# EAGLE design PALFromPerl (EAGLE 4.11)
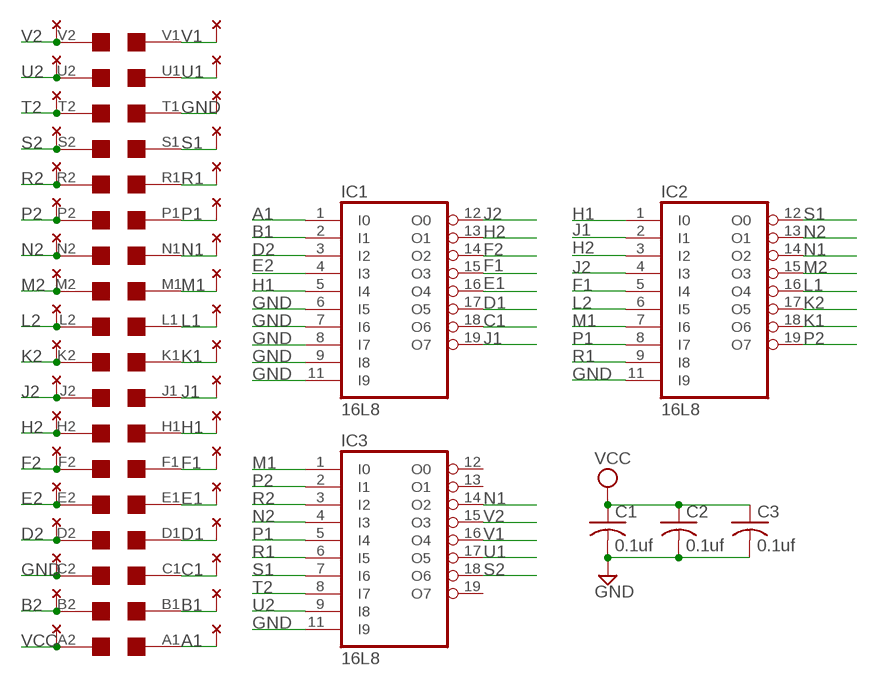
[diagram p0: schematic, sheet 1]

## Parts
C1  0.1uf  C-US050-025X075  [C050-025X075]
C2  0.1uf  C-US050-025X075  [C050-025X075]
C3  0.1uf  C-US050-025X075  [C050-025X075]
IC1  16L8  [DIL20]
IC2  16L8  [DIL20]
IC3  16L8  [DIL20]
U$1  EDGE-2  [EDGE-CON2]
U$4  THRU-HOLE2  [THRU-HOLEB]

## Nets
A1: IC1.1(I0) U$1.A1 U$4.A2
B1: IC1.2(I1) U$1.B1 U$4.B2
B2: U$1.B2 U$4.B1
C1: IC1.18(O6) U$1.C1 U$4.C2
D1: IC1.17(O5) U$1.D1 U$4.D2
D2: IC1.3(I2) U$1.D2 U$4.D1
E1: IC1.16(O4) U$1.E1 U$4.E2
E2: IC1.4(I3) U$1.E2 U$4.E1
F1: IC1.15(O3) IC2.5(I4) U$1.F1 U$4.F2
F2: IC1.14(O2) U$1.F2 U$4.F1
GND: C1.2 C2.2 C3.2 IC1.6(I5) IC1.7(I6) IC1.8(I7) IC1.9(I8) IC1.11(I9) IC2.11(I9) IC3.11(I9) U$1.C2 U$1.T1 U$4.C1 U$4.T2
H1: IC1.5(I4) IC2.1(I0) U$1.H1 U$4.H2
H2: IC1.13(O1) IC2.3(I2) U$1.H2 U$4.H1
J1: IC1.19(O7) IC2.2(I1) U$1.J1 U$4.J2
J2: IC1.12(O0) IC2.4(I3) U$1.J2 U$4.J1
K1: IC2.18(O6) U$1.K1 U$4.K2
K2: IC2.17(O5) U$1.K2 U$4.K1
L1: IC2.16(O4) U$1.L1 U$4.L2
L2: IC2.6(I5) U$1.L2 U$4.L1
M1: IC2.7(I6) IC3.1(I0) U$1.M1 U$4.M2
M2: IC2.15(O3) U$1.M2 U$4.M1
N1: IC2.14(O2) IC3.14(O2) U$1.N1 U$4.N2
N2: IC2.13(O1) IC3.4(I3) U$1.N2 U$4.N1
P1: IC2.8(I7) IC3.5(I4) U$1.P1 U$4.P2
P2: IC2.19(O7) IC3.2(I1) U$1.P2 U$4.P1
R1: IC2.9(I8) IC3.6(I5) U$1.R1 U$4.R2
R2: IC3.3(I2) U$1.R2 U$4.R1
S1: IC2.12(O0) IC3.7(I6) U$1.S1 U$4.S2
S2: IC3.18(O6) U$1.S2 U$4.S1
T2: IC3.8(I7) U$1.T2 U$4.T1
U1: IC3.17(O5) U$1.U1 U$4.U2
U2: IC3.9(I8) U$1.U2 U$4.U1
V1: IC3.16(O4) U$1.V1 U$4.V2
V2: IC3.15(O3) U$1.V2 U$4.V1
VCC: C1.1 C2.1 C3.1 U$1.A2 U$4.A1
Unconnected: IC3.12(O0) IC3.13(O1) IC3.19(O7)

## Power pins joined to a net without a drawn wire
GND: IC1.10(GND) IC2.10(GND) IC3.10(GND)
VCC: IC1.20(VCC) IC2.20(VCC) IC3.20(VCC)

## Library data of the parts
C1-C3 = rcl:C-US: CAPACITOR, American symbol
IC1-IC3 = pal:16L8: PAL
U$1 = dec-con:EDGE-2: Double-Sided DEC edge connector.
U$4 = dec-con:THRU-HOLE2: Thru-Hole addition to double-sided edge connector.

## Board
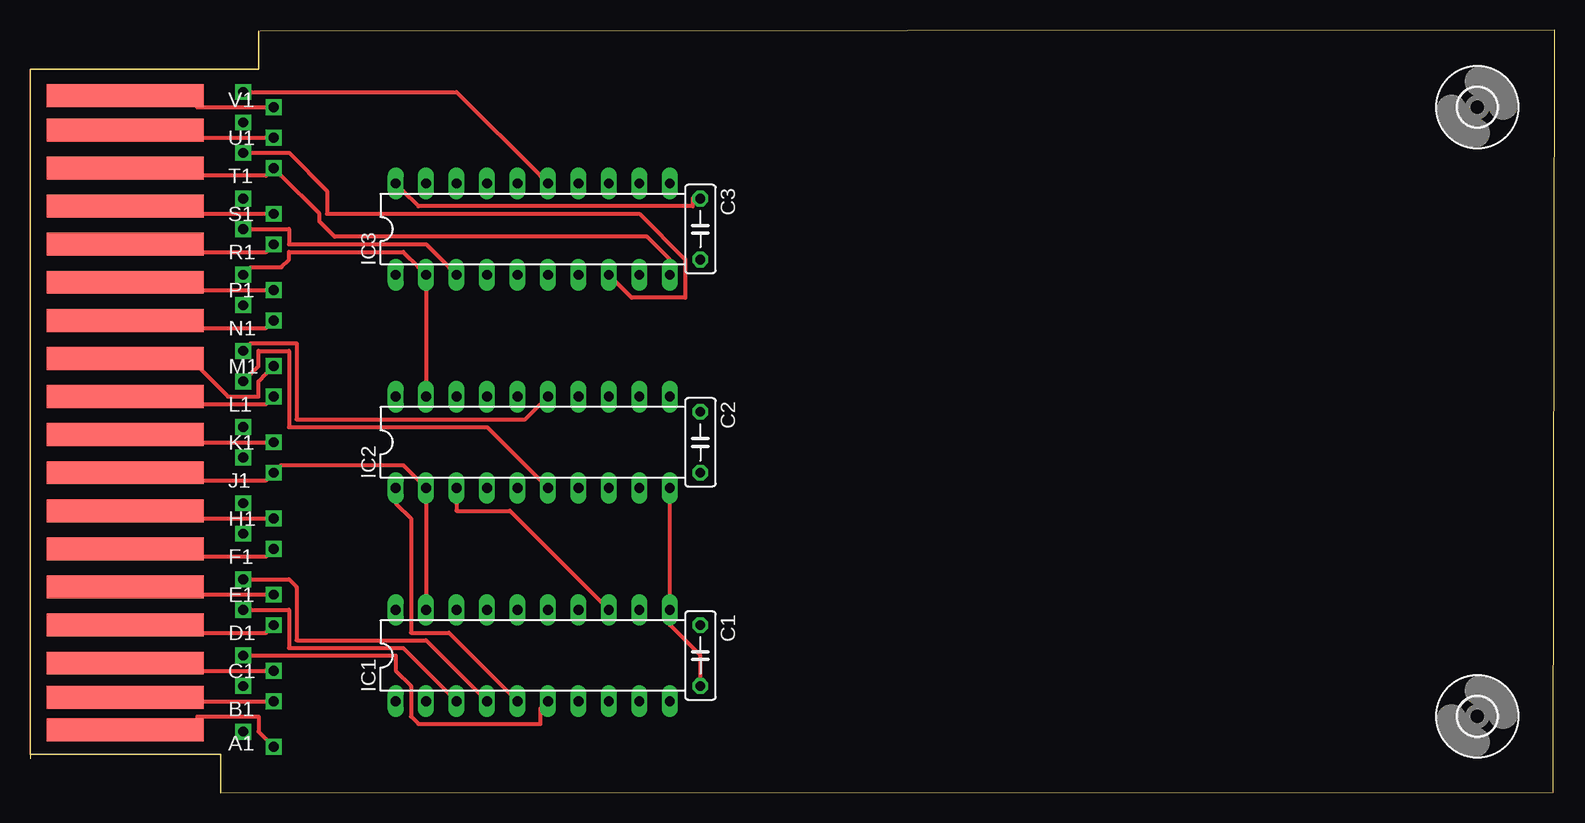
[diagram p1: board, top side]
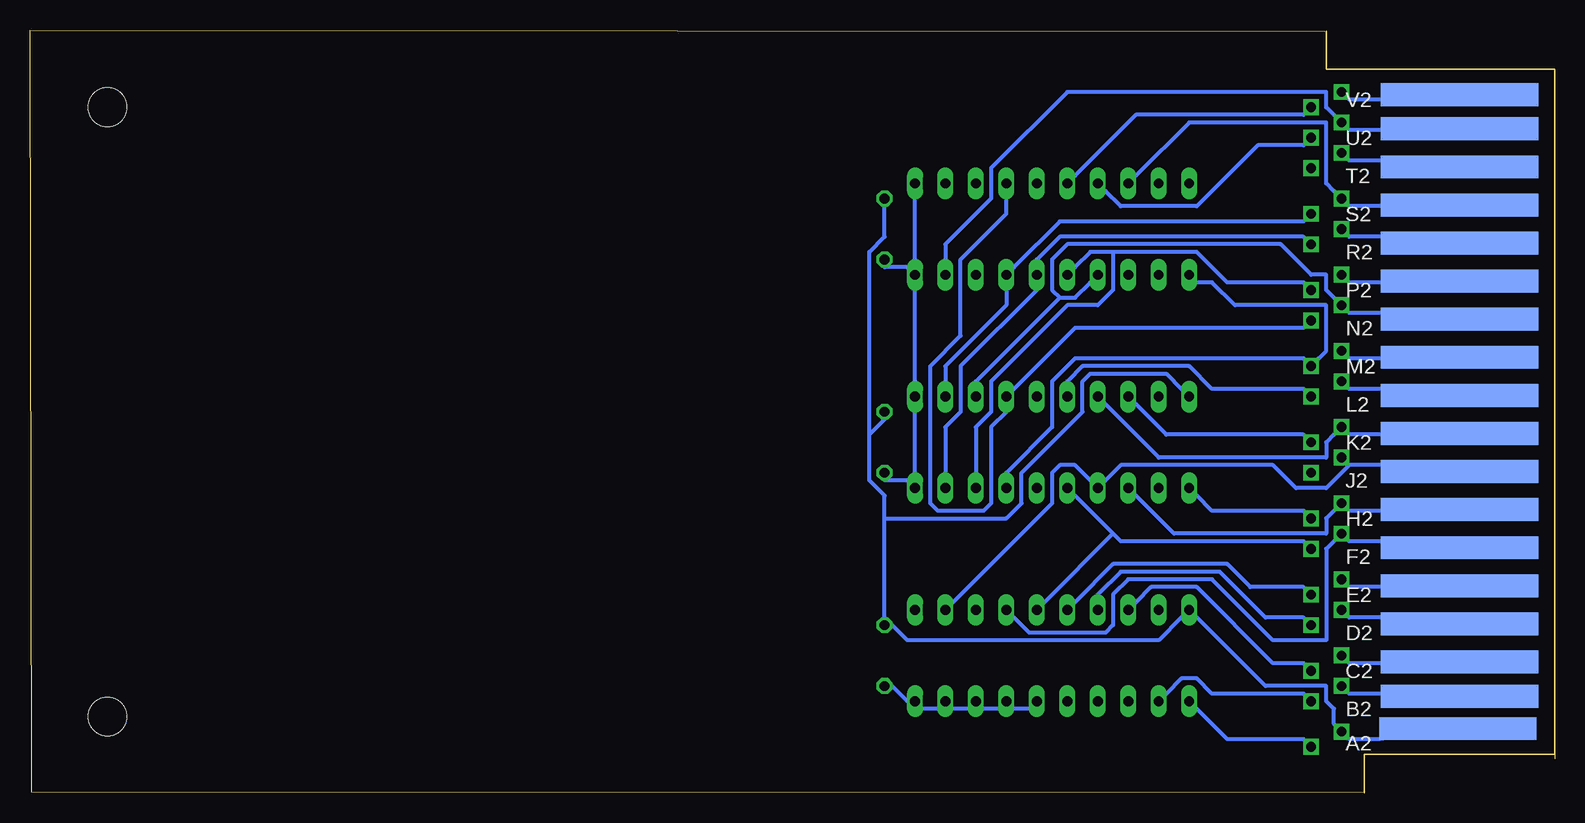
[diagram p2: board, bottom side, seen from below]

Size 127.11 x 63.59 mm. Coordinates in mm from the lower left corner, seen from the top.
Outline: 15.88,0 126.98,0.04 127.11,63.59 19.18,63.5
Outline: 0.01,59.65 0.01,2.83
Copper layers (1*16): Top 0.035mm / dielectric 1.5mm / Bottom 0.035mm
Design rules "10mils": minimum track width 13mil, minimum drill 28mil, track to track 10mil, track to pad 10mil, pad to pad 10mil, via to via 10mil, smd to smd 10mil, copper to edge 40mil, drill to drill 10mil, minimum pad ring 10mil, minimum via ring 8mil, stop-mask expansion 0mil, vias tented up to drill 0mil, thermal gap 10mil

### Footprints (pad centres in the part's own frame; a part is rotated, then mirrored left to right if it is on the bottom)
C050-025X075 = drill 0.813 octagon: 1 -2.54,0; 2 2.54,0
DIL20 = drill 0.813 long: 1 -11.43,-3.81; 2 -8.89,-3.81; 3 -6.35,-3.81; 4 -3.81,-3.81; 5 -1.27,-3.81; 6 1.27,-3.81; 7 3.81,-3.81; 8 6.35,-3.81; 9 8.89,-3.81; 10 11.43,-3.81; 11 11.43,3.81; 12 8.89,3.81; 13 6.35,3.81; 14 3.81,3.81; 15 1.27,3.81; 16 -1.27,3.81; 17 -3.81,3.81; 18 -6.35,3.81; 19 -8.89,3.81; 20 -11.43,3.81
EDGE-CON2 = smd 13.106 x 1.905: A1 7.938,5.239; B1 7.938,7.938; C1 7.938,10.795; D1 7.938,13.97; E1 7.938,17.145; F1 7.938,20.32; H1 7.938,23.495; J1 7.938,26.67; K1 7.938,29.845; L1 7.938,33.02; M1 7.938,36.195; N1 7.938,39.37; P1 7.938,42.545; R1 7.938,45.72; S1 7.938,48.895; T1 7.938,52.07; U1 7.938,55.245; V1 7.938,58.102 | smd 13.106 x 1.905 bottom: A2 8.096,5.34; B2 7.938,8.039; C2 7.938,10.897; D2 7.938,14.072; E2 7.938,17.247; F2 7.938,20.422; H2 7.938,23.597; J2 7.938,26.772; K2 7.938,29.947; L2 7.938,33.122; M2 7.938,36.297; N2 7.938,39.472; P2 7.938,42.647; R2 7.938,45.822; S2 7.938,48.997; T2 7.938,52.172; U2 7.938,55.347; V2 7.938,58.204
3,2 = hole 3.2: 0,0
THRU-HOLEB = drill 0.813 square: A1 17.78,5.08; A2 20.32,3.81; B1 17.78,8.89; B2 20.32,7.62; C1 17.78,11.43; C2 20.32,10.16; D1 17.78,15.24; D2 20.32,13.97; E1 17.78,17.78; E2 20.32,16.51; F1 17.78,21.59; F2 20.32,20.32; H1 17.78,24.13; H2 20.32,22.86; J1 17.78,27.94; J2 20.32,26.67; K1 17.78,30.48; K2 20.32,29.21; L1 17.78,34.29; L2 20.32,33.02; M1 17.78,36.83; M2 20.32,35.56; N1 17.78,40.64; N2 20.32,39.37; P1 17.78,43.18; P2 20.32,41.91; R1 17.78,46.99; R2 20.32,45.72; S1 17.78,49.53; S2 20.32,48.26; T1 17.78,53.34; T2 20.32,52.07; U1 17.78,55.88; U2 20.32,54.61; V1 17.78,58.42; V2 20.32,57.15

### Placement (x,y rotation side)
C1  55.88,11.43 270 top
C2  55.88,29.21 270 top
C3  55.88,46.99 270 top
IC1  41.91,11.43 0 top
IC2  41.91,29.21 0 top
IC3  41.91,46.99 0 top
U$1  0,0 0 top
U$2  [3,2]  120.65,6.35 0 top
U$3  [3,2]  120.65,57.15 0 top
U$4  0,0 0 top

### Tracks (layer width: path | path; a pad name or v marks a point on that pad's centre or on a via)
A1
  Top 0.33: U$4.A2 19.68,4.45 19.05,5.08 19.05,6.35 13.97,6.35 13.97,5.71 U$1.A1
  Bottom 0.33: U$4.A2 20.95,4.45 27.3,4.45 29.84,6.99 IC1.1
B1
  Top 0.33: U$4.B2 19.68,7.62 13.97,7.62 U$1.B1
  Bottom 0.33: U$4.B2 20.95,8.26 28.57,8.26 29.84,9.53 31.11,9.53 32.38,8.26 IC1.2
B2
  Bottom 0.33: U$4.B1 17.14,8.26 13.97,8.26 U$1.B2
C1
  Top 0.33: U$4.C2 19.68,10.16 13.97,10.16 U$1.C1
  Bottom 0.33: U$4.C2 20.95,10.79 23.5,10.79 29.84,17.14 33.66,17.14 34.92,15.88 IC1.18
D1
  Top 0.33: U$4.D2 19.68,13.34 13.97,13.34 U$1.D1
  Bottom 0.33: U$4.D2 20.95,14.61 24.13,14.61 27.94,18.41 36.2,18.41 38.1,16.51 IC1.17
D2
  Top 0.33: IC1.3 34.92,8.26 31.11,12.06 21.59,12.06 21.59,15.24 18.41,15.24 U$4.D1
  Bottom 0.33: U$4.D1 17.14,14.61 13.97,14.61 U$1.D2
E1
  Top 0.33: U$4.E2 19.68,16.51 13.97,16.51 U$1.E1
  Bottom 0.33: U$4.E2 20.95,17.14 25.4,17.14 27.3,19.05 36.83,19.05 40.01,15.88 IC1.16
E2
  Top 0.33: IC1.4 37.47,8.26 33.02,12.7 22.23,12.7 22.23,17.14 21.59,17.78 18.41,17.78 U$4.E1
  Bottom 0.33: U$4.E1 17.14,17.14 13.97,17.14 U$1.E2
F1
  Top 0.33: U$1.F1 13.97,19.68 19.68,19.68 U$4.F2
  Bottom 0.33: 36.83,21.59 40.01,24.77 IC2.5 | 36.83,21.59 36.2,20.95 20.95,20.95 U$4.F2 | 36.83,21.59 42.55,15.88 IC1.15
F2
  Bottom 0.33: U$1.F2 13.97,20.95 17.14,20.95 U$4.F1 18.41,20.95 19.05,20.32 19.05,12.7 23.5,12.7 28.57,17.78 35.56,17.78 36.83,16.51 36.83,13.97 37.47,13.34 43.81,13.34 45.09,14.61 IC1.14
GND
  Top 0.33: U$1.T1 13.97,51.44 19.68,51.44 U$4.T2 20.95,51.44 24.13,48.26 24.13,47.62 25.4,46.35 51.44,46.35 53.34,44.45 IC3.10 | C1.2 55.88,9.53 55.88,11.43 53.34,13.97 IC1.11 53.34,16.51 53.34,24.13 IC2.10 | U$4.C1 18.41,11.43 30.48,11.43 30.48,10.16 31.75,8.89 31.75,6.35 32.38,5.71 42.55,5.71 42.55,6.99 IC1.6
  Bottom 0.33: U$4.C1 17.14,10.79 13.97,10.79 U$1.C2 | IC1.6 43.81,6.99 45.09,6.99 IC1.7 46.35,6.99 47.62,6.99 IC1.8 48.9,6.99 50.16,6.99 IC1.9 51.44,6.99 52.7,6.99 IC1.10 53.98,7.62 55.24,8.89 C1.2 | IC3.10 53.98,43.81 55.88,43.81 C3.2 | C2.2 55.88,26.04 53.98,26.04 IC2.10 53.34,26.67 53.34,31.75 IC2.11 53.34,34.29 53.34,41.91 IC3.10 | IC3.11 53.34,49.53 53.34,44.45 IC3.10
H1
  Top 0.33: IC1.5 40.01,8.26 34.92,13.34 31.75,13.34 31.75,22.86 30.48,24.13 IC2.1 | U$1.H1 13.97,22.86 19.68,22.86 U$4.H2
  Bottom 0.33: U$4.H2 20.95,23.5 28.57,23.5 29.84,24.77 IC2.1
H2
  Top 0.33: IC1.13 47.62,15.88 40.01,23.5 35.56,23.5 35.56,24.13 IC2.3
  Bottom 0.33: U$1.H2 13.97,23.5 17.14,23.5 U$4.H1 18.41,23.5 19.05,22.86 19.05,21.59 31.75,21.59 34.92,24.77 IC2.3
J1
  Top 0.33: IC1.19 33.02,16.51 33.02,24.13 IC2.2 32.38,26.04 31.11,27.3 20.95,27.3 U$4.J2 19.68,26.04 13.97,26.04 U$1.J1
J2
  Bottom 0.33: IC1.12 50.16,15.88 41.91,24.13 41.91,26.67 41.27,27.3 40.01,27.3 38.73,26.04 IC2.4 37.47,26.04 36.2,27.3 23.5,27.3 21.59,25.4 19.05,25.4 17.14,27.3 | 17.14,27.3 13.97,27.3 U$1.J2 | 17.14,27.3 U$4.J1 17.14,27.3
K1
  Top 0.33: U$4.K2 19.68,29.21 13.97,29.21 U$1.K1
  Bottom 0.33: U$4.K2 20.95,29.84 32.38,29.84 34.92,32.38 IC2.18
K2
  Bottom 0.33: U$1.K2 13.97,29.84 17.14,29.84 U$4.K1 18.41,29.84 19.05,29.21 19.05,27.94 33.02,27.94 37.47,32.38 IC2.17
L1
  Top 0.33: U$4.L2 19.68,32.38 13.97,32.38 U$1.L1
  Bottom 0.33: U$4.L2 20.95,33.66 28.57,33.66 30.48,35.56 39.37,35.56 40.64,34.29 IC2.16
L2
  Top 0.33: IC2.6 42.55,26.04 38.1,30.48 21.59,30.48 21.59,36.83 19.05,36.83 19.05,35.56 18.41,34.92 U$4.L1
  Bottom 0.33: U$4.L1 17.14,33.66 13.97,33.66 U$1.L2
M1
  Top 0.33: U$1.M1 13.97,35.56 16.51,33.02 19.05,33.02 19.05,34.29 19.68,34.92 U$4.M2
  Bottom 0.33: IC2.7 45.72,26.67 41.91,30.48 41.91,34.29 40.01,36.2 20.95,36.2 U$4.M2 19.68,36.2 19.05,36.83 19.05,40.64 26.67,40.64 28.57,42.55 29.84,42.55 IC3.1
M2
  Top 0.33: IC2.15 42.55,32.38 41.27,31.11 22.23,31.11 22.23,37.47 18.41,37.47 U$4.M1
  Bottom 0.33: U$4.M1 17.14,36.2 13.97,36.2 U$1.M2
N1
  Top 0.33: U$1.N1 13.97,38.73 19.68,38.73 U$4.N2
  Bottom 0.33: U$4.N2 20.95,38.73 40.01,38.73 45.09,33.66 IC2.14 45.72,31.75 46.99,30.48 46.99,24.13 47.62,23.5 51.44,23.5 52.07,24.13 52.07,35.56 49.53,38.1 49.53,44.45 45.72,48.26 45.72,49.53 IC3.14
N2
  Bottom 0.33: 41.27,41.27 40.01,41.27 38.73,42.55 IC3.4 | 41.27,41.27 48.26,34.29 IC2.13 | U$1.N2 13.97,40.01 17.14,40.01 U$4.N1 18.41,41.27 19.05,41.91 19.05,43.18 20.32,43.18 22.86,45.72 40.64,45.72 41.91,44.45 41.91,41.91 41.27,41.27
P1
  Top 0.33: U$1.P1 13.97,41.91 19.68,41.91 U$4.P2
  Bottom 0.33: 36.83,45.09 38.73,45.09 40.01,43.81 IC3.5 | 36.83,45.09 29.84,45.09 27.3,42.55 20.95,42.55 U$4.P2 | 36.83,45.09 36.83,41.91 38.1,40.64 40.64,40.64 46.99,34.29 46.99,31.75 48.26,30.48 48.26,26.67 IC2.8
P2
  Top 0.33: IC2.19 33.02,34.29 33.02,41.91 IC3.2 32.38,43.81 31.11,45.09 21.59,45.09 21.59,44.45 20.95,43.81 18.41,43.81 U$4.P1
  Bottom 0.33: U$4.P1 17.14,42.55 13.97,42.55 U$1.P2
R1
  Top 0.33: U$1.R1 13.97,45.09 19.68,45.09 U$4.R2
  Bottom 0.33: U$4.R2 20.95,46.35 41.27,46.35 43.18,44.45 IC3.6 43.18,41.91 49.53,35.56 49.53,31.75 50.8,30.48 50.8,26.67 IC2.9
R2
  Top 0.33: IC3.3 34.92,43.81 33.02,45.72 21.59,45.72 21.59,46.99 18.41,46.99 U$4.R1
  Bottom 0.33: U$4.R1 17.14,46.35 13.97,46.35 U$1.R2
S1
  Top 0.33: U$1.S1 13.97,48.26 19.68,48.26 U$4.S2
  Bottom 0.33: IC2.12 50.8,34.29 50.8,35.56 45.72,40.64 45.72,41.91 IC3.7 45.09,43.81 41.27,47.62 20.95,47.62 U$4.S2
S2
  Bottom 0.33: U$1.S2 13.97,48.9 17.14,48.9 U$4.S1 18.41,50.16 19.05,50.8 19.05,55.88 30.48,55.88 34.92,51.44 IC3.18
T2
  Top 0.33: IC3.8 48.9,42.55 50.16,41.27 54.61,41.27 54.61,44.45 50.8,48.26 24.77,48.26 24.77,50.16 21.59,53.34 18.41,53.34 U$4.T1
  Bottom 0.33: U$4.T1 17.14,52.7 13.97,52.7 U$1.T2
U1
  Top 0.33: U$4.U2 19.68,54.61 13.97,54.61 U$1.U1
  Bottom 0.33: U$4.U2 20.95,53.98 24.77,53.98 29.84,48.9 36.2,48.9 37.47,50.16 IC3.17
U2
  Bottom 0.33: U$1.U2 13.97,55.24 17.14,55.24 U$4.U1 18.41,56.52 19.05,57.15 19.05,58.42 40.64,58.42 46.99,52.07 46.99,49.53 50.8,45.72 50.8,44.45 IC3.9
V1
  Top 0.33: U$4.V2 19.68,57.15 13.97,57.15 13.97,57.78 U$1.V1
  Bottom 0.33: U$4.V2 20.95,56.52 34.92,56.52 40.01,51.44 IC3.16
V2
  Top 0.33: IC3.15 42.55,51.44 35.56,58.42 18.41,58.42 U$4.V1
  Bottom 0.33: U$4.V1 17.14,57.78 13.97,57.78 U$1.V2
VCC
  Top 0.33: IC3.20 31.11,50.16 32.38,48.9 55.24,48.9 55.24,49.53 C3.1
  Bottom 0.33: U$1.A2 14.61,4.45 17.14,4.45 U$4.A1 18.41,5.71 18.41,6.99 19.05,7.62 19.05,8.89 24.13,8.89 29.84,14.61 IC1.20 31.11,14.61 33.02,12.7 53.98,12.7 55.24,13.97 C1.1 55.88,14.61 55.88,22.86 | 55.88,22.86 55.88,24.77 57.15,26.04 57.15,29.84 | 57.15,29.84 55.88,31.11 C2.1 | 55.88,22.86 45.72,22.86 44.45,24.13 44.45,26.67 39.37,31.75 39.37,34.29 38.73,34.92 32.38,34.92 31.11,33.66 IC2.20 | 57.15,29.84 57.15,45.09 55.88,46.35 55.88,48.9 C3.1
